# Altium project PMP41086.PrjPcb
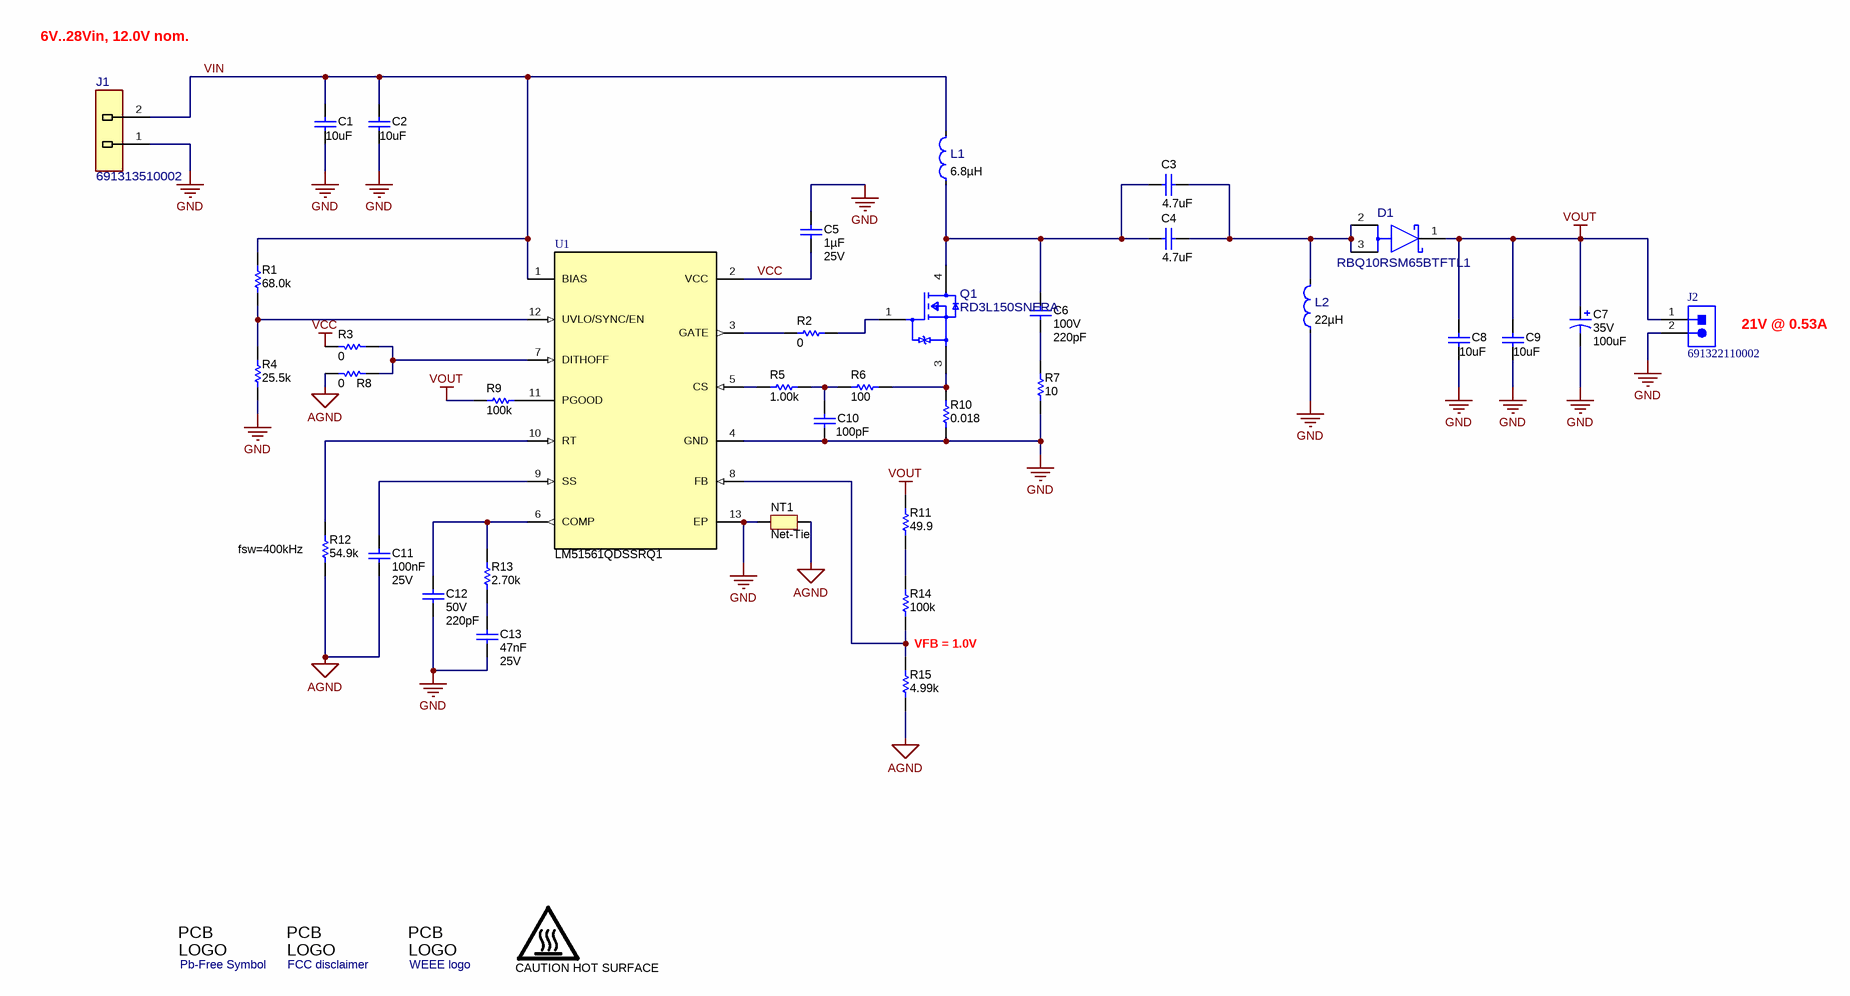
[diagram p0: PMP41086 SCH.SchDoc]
TID: N/A; TechSupport: http://www.ti.com/support; SCH_Rev: E1; PRJ_Title: Change in menu Project|Project Options|Parameters; PRJ_Number: PMP41086; PRJ_Customer: Public Release; PCB_Rev: E1; PCB_Layout: Who did the Layout?; CopyrightYear: 2023
1 sheet, 40 parts. Net scope: global (net labels, ports and power ports of the same name join across sheets).
Board file: PMP41086 PCB.PcbDoc

## Sheet PMP41086 SCH.SchDoc
size 431 x 279 mm; Date: Not shown in title block; ApprovedBy: Not shown in title block; CheckedBy: Not shown in title block; Author: Not shown in title block; CompanyName: Not shown in title block; Engineer: Not shown in title block; Organization: Not shown in title block; Address1: Not shown in title block; Address2: Not shown in title block; Address3: Not shown in title block; Address4: Not shown in title block; DocumentNumber: 1; Revision: Use project parameter SCH_Rev; SheetNumber: 1; SheetTotal: 1; PageSetup: Record=PageOptions¦CenterHorizontal=True¦CenterVertical=True¦PrintScale=1.00¦XCorrection=1.00¦YCorrection=1.00¦PrintKind=0¦BorderSize=5000000¦LeftOffset=0¦BottomOffset=0¦Orientation=2¦PaperLength=1000¦PaperWidth=1000¦Scale=100¦PaperSource=15¦PrintQuality=600¦MediaType=1¦DitherType=10¦PaperKind=Letter¦PrintScaleMode=1

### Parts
C1  ValueDisplayed: 10uF  [1210_280]  (hidden comment: UMK325AB7106KMHT)
C2  ValueDisplayed: 10uF  [1210_280]  (hidden comment: UMK325AB7106KMHT)
C3  ValueDisplayed: 4.7uF  [1210_280]  (hidden comment: CGA6P3X7R1H475K250AB)
C4  ValueDisplayed: 4.7uF  [1210_280]  (hidden comment: CGA6P3X7R1H475K250AB)
C5  Cap_F: 1µF  VDC_V: 25V  [0603]  (hidden comment: GCM188R71E105KA64D)
C6  VDC_V: 100V  ValueDisplayed: 220pF  [0603]  (hidden comment: GCM1885C2A221JA16D)
C7  VDC_V: 35V  ValueDisplayed: 100uF  [SM_RADIAL_D8]  (hidden comment: EEE-FK1V101XP)
C8  ValueDisplayed: 10uF  [1210_280]  (hidden comment: UMK325AB7106KMHT)
C9  ValueDisplayed: 10uF  [1210_280]  (hidden comment: UMK325AB7106KMHT)
C10  ValueDisplayed: 100pF  [0603]  (hidden comment: CGA3E2NP01H101J080AA)
C11  Cap_F: 100nF  VDC_V: 25V  [0603]  (hidden comment: CGA3E2X7R1E104K080AA)
C12  VDC_V: 50V  ValueDisplayed: 220pF  [0603]  (hidden comment: 06035A221JAT2A)
C13  Cap_F: 47nF  VDC_V: 25V  [0603]  (hidden comment: GCM188R71E473KA37D)
D1  RBQ10RSM65BTFTL1  [FP-STPS1045SF_PSMC-MFG]
J1  691313510002  [FP-691313510002_TRM_BLK_HDR2-MFG]
J2  691322110002  [691322110002]
L1  Ind_H: 6.8µH  [FP-SPM7054VT- 470M-D_STM_7MM5_7MM0-0]  (hidden comment: SPM7054VC-6R8M-D)
L2  Ind_H: 22µH  [FP-SPM7054VT- 470M-D_STM_7MM5_7MM0-0]  (hidden comment: SPM7054VC-220M-D)
Logo1  Pb-Free Symbol  [Pb-Free_Overlay_Medium]  (no BOM)
Logo2  FCC disclaimer  [FCC_disclaimer]  (no BOM)
Logo3  WEEE logo  [WEEE_Minimum]  (no BOM)
LOGO4  CAUTION HOT SURFACE  [IEC_HotSurface_Small]  (no BOM)
NT1  Net-Tie  [NetTie_0603]  (net tie, no BOM)
Q1  RD3L150SNFRA  [FP-RD3P08BBD_TO252-MFG]
R1  ValueDisplayed: 68.0k  [0603]  (hidden comment: RC0603FR-0768KL)
R2  ValueDisplayed: 0  [0603]  (hidden comment: RC0603JR-070RL)
R3  ValueDisplayed: 0  [0603]  (hidden comment: ERJ-3GEY0R00V)
R4  ValueDisplayed: 25.5k  [0603]  (hidden comment: CRCW060325K5FKEA)
R5  ValueDisplayed: 1.00k  [0603]  (hidden comment: CRCW06031K00FKEA)
R6  ValueDisplayed: 100  [0603]  (hidden comment: CRCW0603100RFKEA)
R7  ValueDisplayed: 10  [0603]  (hidden comment: CRCW060310R0JNEA)
R8  ValueDisplayed: 0  [0603]  (hidden comment: ERJ-3GEY0R00V)
R9  ValueDisplayed: 100k  [0603]  (hidden comment: CRCW0603100KFKEA)
R10  ValueDisplayed: 0.018  [1206]  (hidden comment: CSR1206FK18L0)
R11  ValueDisplayed: 49.9  [0603]  (hidden comment: CRCW060349R9FKEA)
R12  ValueDisplayed: 54.9k  [0603]  (hidden comment: CRCW060354K9FKEA)
R13  ValueDisplayed: 2.70k  [0603]  (hidden comment: RC0603FR-072K7L)
R14  ValueDisplayed: 100k  [0603]  (hidden comment: CRCW0603100KFKEA)
R15  ValueDisplayed: 4.99k  [0603]  (hidden comment: CRCW06034K99FKEA)
U1  LM51561QDSSRQ1  [DSS0012C]

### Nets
AGND: C11.2 NT1.1 R8.2 R12.1 R15.1
GND: C1.2 C2.2 C5.1 C7.2(-) C8.2 C9.2 C10.2 C12.2 C13.2 J1.1 J2.2 L2.1 NT1.2 R4.1 R7.1 R10.1 U1.4(GND) U1.13(EP)
VCC: C5.2 R3.2 U1.2(VCC)
VOUT: C7.1(+) C8.1 C9.1 D1.1(K) J2.1 R9.1 R11.2
VIN: C1.1 C2.1 J1.2 L1.2 R1.2 U1.1(BIAS)
NetC3_1: C3.1 C4.1 D1.2(A) D1.3(A) L2.2
NetC3_2: C3.2 C4.2 C6.1 L1.1 Q1.4(DRAIN)
NetC6_2: C6.2 R7.2
NetC10_1: C10.1 R5.2 R6.1
NetC11_1: C11.1 U1.9(SS)
NetC12_1: C12.1 R13.2 U1.6(COMP)
NetC13_1: C13.1 R13.1
NetQ1_1: Q1.1(GATE) R2.2
NetQ1_3: Q1.3(SOURCE) R6.2 R10.2
NetR1_1: R1.1 R4.2 U1.12(UVLO/SYNC/EN)
NetR2_1: R2.1 U1.3(GATE)
NetR3_1: R3.1 R8.1 U1.7(DITHOFF)
NetR5_1: R5.1 U1.5(CS)
NetR9_2: R9.2 U1.11(PGOOD)
NetR11_1: R11.1 R14.2
NetR12_2: R12.2 U1.10(RT)
NetR14_1: R14.1 R15.2 U1.8(FB)

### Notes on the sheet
- 6V..28Vin, 12.0V nom.
- (near J2) 21V @ 0.53A
- (near R12) fsw=400kHz
- VFB = 1.0V

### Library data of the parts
C1 C2 C8 C9 = CMP-0009258-1: CAP, CERM, 10 uF, 50 V, +/- 10%, X7R, AEC-Q200 Grade 1, 1210; Manufacturer: Taiyo Yuden; TaMin_C: -55°C; Polarized: N; SizeAreaWB_mm2: 14.7; Value1: Unknown; U/M: EA; Value: 10uF; TaMax_C: 125°C; SizeZ_mm: 2.8; SizeX_mm: 3.2; SizeY_mm: 2.5; Cap_Case: 1210; Value2: 50V; SizeArea_mm2: 8; AEC Qualified: Y; Cap_F: 10µF; AEC Grade: 1; AEC Category: Q200
C3 C4 = CMP-0009162-1: CAP, CERM, 4.7 uF, 50 V, +/- 10%, X7R, AEC-Q200 Grade 1, 1210; Manufacturer: TDK; TaMin_C: -55°C; ESR_ohm: 3.166m; Polarized: N; SizeAreaWB_mm2: 14.7; Value1: 0.003166 ohm; U/M: EA; Value: 4.7uF; TaMax_C: 125°C; SizeZ_mm: 2.8; SizeX_mm: 3.2; SizeY_mm: 2.5; Value2: 50V; SizeArea_mm2: 8; AEC Qualified: Y; Cap_F: 4.7µF; IRMS_A: 4.13311A; AEC Grade: 1; AEC Category: Q200
C5 = CMP-0007139-4: CAP, CERM, 1 uF, 25 V, +/- 10%, X7R, AEC-Q200 Grade 1, 0603; Manufacturer: MuRata; TaMin_C: -55°C; Polarized: N; SizeAreaWB_mm2: 4.68; Value1: Unknown; U/M: EA; Value: 1uF; TaMax_C: 125°C; SizeZ_mm: 1; SizeX_mm: 1.6; SizeY_mm: 0.8; SizeArea_mm2: 1.28; AEC Qualified: Y; AEC Category: Q200
C6 = CMP-0860912-1: CAP, CERM, 220 pF, 100 V,+/- 5%, C0G/NP0, AEC-Q200 Grade 1, 0603; Manufacturer: MuRata; SizeArea_mm2: 1.28; AEC Grade: 1; SizeAreaWB_mm2: 4.68; Value: 220pF; U/M: EA; TaMax_C: 125°C; TaMin_C: -55°C; SizeY_mm: 0.8; AEC Qualified: Y; AEC Category: Q200; Polarized: N; SizeX_mm: 1.6
C7 = CMP-0010724-1: CAP, AL, 100 uF, 35 V, +/- 20%, 0.34 ohm, AEC-Q200 Grade 2, SMD; Manufacturer: Panasonic; TaMin_C: -55°C; ESR_ohm: 0.34; Polarized: Y; SizeAreaWB_mm2: 84.28; U/M: EA; Value: 100uF; TaMax_C: 105°C; SizeZ_mm: 7.7; SizeX_mm: 7.8; SizeY_mm: 6.6; Cap_Case: D8; SizeArea_mm2: 51.48; CompType: Capacitor; Cap_F: 100µF; IRMS_A: 280mA; AEC Grade: 2; AEC Category: Q200
C10 = CMP-0007075-1: CAP, CERM, 100 pF, 50 V, +/- 5%, C0G/NP0, AEC-Q200 Grade 0, 0603; Manufacturer: TDK; TaMin_C: -55°C; Polarized: N; SizeAreaWB_mm2: 4.68; Value1: Unknown; U/M: EA; Value: 100pF; TaMax_C: 150°C; SizeZ_mm: 1; SizeX_mm: 1.6; SizeY_mm: 0.8; Value2: 50V; SizeArea_mm2: 1.28; AEC Qualified: Y; AEC Grade: 0; AEC Category: Q200
C11 = CMP-0007077-3: CAP, CERM, 0.1 uF, 25 V, +/- 10%, X7R, AEC-Q200 Grade 1, 0603; Manufacturer: TDK; TaMin_C: -55°C; Polarized: N; SizeAreaWB_mm2: 4.68; Value1: Unknown; U/M: EA; Value: 0.1uF; TaMax_C: 125°C; SizeZ_mm: 1; SizeX_mm: 1.6; SizeY_mm: 0.8; SizeArea_mm2: 1.28; AEC Qualified: Y; AEC Category: Q200
C12 = CMP-0006777-1: CAP, CERM, 220 pF, 50 V, +/- 5%, C0G/NP0, 0603; Manufacturer: AVX; TaMin_C: -55°C; ESR_ohm: 0.083; Polarized: N; SizeAreaWB_mm2: 4.68; Value1: 0.083 ohm; U/M: EA; Value: 220pF; TaMax_C: 125°C; SizeZ_mm: 1; SizeX_mm: 1.6; SizeY_mm: 0.8; SizeArea_mm2: 1.28; AEC Category: Q200
C13 = CMP-0007141-5: CAP, CERM, 0.047 uF, 25 V, +/- 10%, X7R, AEC-Q200 Grade 1, 0603; Manufacturer: MuRata; TaMin_C: -55°C; Polarized: N; SizeAreaWB_mm2: 4.68; Value1: Unknown; U/M: EA; TaMax_C: 125°C; SizeZ_mm: 1; SizeX_mm: 1.6; SizeY_mm: 0.8; SizeArea_mm2: 1.28; AEC Qualified: Y; AEC Category: Q200
D1 = CMP-0098014-1: DIODE SCHOTTKY 65V 10A TO277A; Manufacturer: Rohm; TJmax_C: 175°C; Vf_V: 45V; SizeZ_mm: 1.2mm
J1 = CMP-0074821-1: TERM BLK HDR 5.08MM HORZ PCB 2P; Manufacturer: Wurth Electronics; Row_Count: 1; Voltage_V: 300V; Current_A: 20A; ContactFinish: Tin
J2 = 691322110002: WR-TBL Serie 3221 Horizontal PCB Header, Pluggable, THT, pitch 3.5mm, 2p; Manufacturer: Wurth Elektronik; Modularity: No; Pin Number: 2; Rated Current [UL]: 10A; Working Voltage [UL]: 300VAC
L1 = CMP-0088010-1: FIXED IND 6.8UH 7.5A 0.024OHM SM; Manufacturer: TDK; Symbol Name: SPM7054VC-220M-D; AEC Grade: Grade 0; DCR_ohm: 0.1672; AEC Qualified: Yes; SizeZ_mm: 5.4mm
L2 = CMP-0088010-1: FIXED IND 22UH 4A 0.0652OHM SMD; Manufacturer: TDK; AEC Grade: Grade 0; DCR_ohm: 0.1672; AEC Qualified: Yes; SizeZ_mm: 5.4mm
Logo1 = CMP-0074839-1: SymbolCreator: a0412235
Logo2 = CMP-0074847-1: FCC_disclaimer
Logo3 = CMP-0074769-1
LOGO4 = CMP-0074837-1: IEC 61010-1 Hot Surface Warning; Library Reference: IEC_HotSurface; SymbolCreator: a0412235
NT1 = Net-Tie: Single point connection between nets.; SymbolCreator: codlsc
Q1 = CMP-0093637-1: MOSFET N-CH 60V 15A TO252; Manufacturer: Rohm; Number Of N Channels: 1; TJmax_C: +150°C; Input Capacitace At Vds: 1940pF @ 50V
R1 = CMP-0023239-1: RES, 68.0 k, 1%, 0.1 W, 0603; Manufacturer: Yageo America; Power_W: 100mW; TempCo: 200 ppm/C; Value_Code: 68k0; U/M: EA; Value: 68.0k; Res_ohm: 68k; SizeX_mm: 1.6; SizeY_mm: 0.8; SizeZ_mm: 1; Value2: 0.1W; SizeArea_mm2: 1.28; VDC_V: 150V; AEC Category: Q200
R2 = CMP-0025885-5: RES, 0, 5%, 0.1 W, 0603; Manufacturer: Yageo; Power_W: 100mW; TempCo: 200 ppm/C; Value_Code: 0000; Value: 0; EIA_Code: E24; SizeX_mm: 1.6; SizeZ_mm: 1; Value2: 0.1W; SizeArea_mm2: 1.28; AEC Qualified: N; VDC_V: 75V; AEC Category: Q200; SizeY_mm: 0.8; SizeAreaWB_mm2: 4.68
R3 R8 = CMP-0025874-4: RES, 0, 5%, 0.1 W, AEC-Q200 Grade 0, 0603; Manufacturer: Panasonic; Power_W: 100mW; TempCo: 600 ppm/C; Value_Code: 0000; Value: 0; EIA_Code: E24; SizeX_mm: 1.6; SizeY_mm: 0.8; SizeZ_mm: 1; Value2: 0.1W; SizeArea_mm2: 1.28; AEC Qualified: Y; VDC_V: 50V; AEC Category: Q200; SizeAreaWB_mm2: 4.68
R4 = CMP-0022242-4: RES, 25.5 k, 1%, 0.1 W, AEC-Q200 Grade 0, 0603; Manufacturer: Vishay-Dale; Power_W: 100mW; TempCo: 100 ppm/C; Value_Code: 25k5; Value: 25.5k; EIA_Code: E96; SizeX_mm: 1.6; SizeY_mm: 0.8; SizeZ_mm: 1; Value2: 0.1W; SizeArea_mm2: 1.28; AEC Qualified: Y; VDC_V: 75V; AEC Category: Q200; AEC Grade: 0
R5 = CMP-0022109-5: RES, 1.00 k, 1%, 0.1 W, AEC-Q200 Grade 0, 0603; Manufacturer: Vishay-Dale; Power_W: 100mW; TempCo: 100 ppm/C; Value_Code: 1k00; Value: 1.00k; EIA_Code: E96; Res_ohm: 1k; SizeX_mm: 1.6; SizeY_mm: 0.8; SizeZ_mm: 1; Value2: 0.1W; SizeArea_mm2: 1.28; AEC Qualified: Y; VDC_V: 75V; AEC Category: Q200; AEC Grade: 0
R6 = CMP-0021991-4: RES, 100, 1%, 0.1 W, AEC-Q200 Grade 0, 0603; Manufacturer: Vishay-Dale; Power_W: 100mW; TempCo: 100 ppm/C; Value_Code: 100R; Value: 100; EIA_Code: E96; SizeX_mm: 1.6; SizeY_mm: 0.8; SizeZ_mm: 1; Value2: 0.1W; SizeArea_mm2: 1.28; AEC Qualified: Y; VDC_V: 75V; AEC Category: Q200; AEC Grade: 0
R7 = CMP-0025703-4: RES, 10, 5%, 0.1 W, AEC-Q200 Grade 0, 0603; Manufacturer: Vishay-Dale; Power_W: 100mW; TempCo: 200 ppm/C; Value_Code: 10R0; Value: 10; EIA_Code: E24; SizeX_mm: 1.6; SizeY_mm: 0.8; SizeZ_mm: 1; Value2: 0.1W; SizeArea_mm2: 1.28; AEC Qualified: Y; VDC_V: 75V; AEC Category: Q200; AEC Grade: 0
R9 R14 = CMP-0021990-4: RES, 100 k, 1%, 0.1 W, AEC-Q200 Grade 0, 0603; Manufacturer: Vishay-Dale; Power_W: 100mW; TempCo: 100 ppm/C; Value: 100k; EIA_Code: E96; SizeX_mm: 1.6; SizeY_mm: 0.8; SizeZ_mm: 1; Value2: 0.1W; SizeArea_mm2: 1.28; AEC Qualified: Y; VDC_V: 75V; AEC Category: Q200; AEC Grade: 0
R10 = CMP-0017261-1: RES, 0.018, 1%, 0.5 W, 1206; Manufacturer: Stackpole Electronics Inc; Power_W: 500mW; TempCo: 100 ppm/C; Value_Code: R018; U/M: EA; Value: 0.018; EIA_Code: E96; Res_ohm: 0.025; SizeX_mm: 3.2; SizeY_mm: 1.6; SizeZ_mm: 1.35; Value2: 0.5W; SizeArea_mm2: 5.12; AEC Category: Q200
R11 = CMP-0022448-4: RES, 49.9, 1%, 0.1 W, AEC-Q200 Grade 0, 0603; Manufacturer: Vishay-Dale; Power_W: 100mW; TempCo: 100 ppm/C; Value_Code: 49R9; Value: 49.9; EIA_Code: E96; SizeX_mm: 1.6; SizeY_mm: 0.8; SizeZ_mm: 1; Value2: 0.1W; SizeArea_mm2: 1.28; AEC Qualified: Y; VDC_V: 75V; AEC Category: Q200; AEC Grade: 0
R12 = CMP-0022494-4: RES, 54.9 k, 1%, 0.1 W, AEC-Q200 Grade 0, 0603; Manufacturer: Vishay-Dale; Power_W: 100mW; TempCo: 100 ppm/C; Value_Code: 54k9; Value: 54.9k; EIA_Code: E96; SizeX_mm: 1.6; SizeY_mm: 0.8; SizeZ_mm: 1; Value2: 0.1W; SizeArea_mm2: 1.28; AEC Qualified: Y; VDC_V: 75V; AEC Category: Q200; AEC Grade: 0
R13 = CMP-0022996-3: RES, 2.70 k, 1%, 0.1 W, 0603; Manufacturer: Yageo America; Power_W: 100mW; TempCo: 200 ppm/C; Value_Code: 2k70; U/M: EA; Value: 2.70k; Res_ohm: 2.7k; SizeX_mm: 1.6; SizeY_mm: 0.8; SizeZ_mm: 1; Value2: 0.1W; SizeArea_mm2: 1.28; VDC_V: 150V; AEC Category: Q200
R15 = CMP-0022458-4: RES, 4.99 k, 1%, 0.1 W, AEC-Q200 Grade 0, 0603; Manufacturer: Vishay-Dale; Power_W: 100mW; TempCo: 100 ppm/C; Value_Code: 4k99; Value: 4.99k; EIA_Code: E96; SizeX_mm: 1.6; SizeY_mm: 0.8; SizeZ_mm: 1; Value2: 0.1W; SizeArea_mm2: 1.28; AEC Qualified: Y; VDC_V: 75V; AEC Category: Q200; AEC Grade: 0
U1 = CMP-0860749-1: 2.2-MHz Wide VIN 65-V Non-synchronous Boost/SEPIC/Flyback Controller with Dual Random Spread Spectrum, DSS0012C (WSON-12); Alternate Manufacturer: Texas Instruments; Alternate PartNumber: LM51561QDSSTQ1; SizeArea_mm2: 6; SizeY_mm: 3; CompType: IC; AEC Category: Q200; AEC Qualified: Y; SizeAreaWB_mm2: 12; SizeZ_mm: 0.8; SizeX_mm: 2

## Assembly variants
001: not fitted C6 C7 R7 R8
